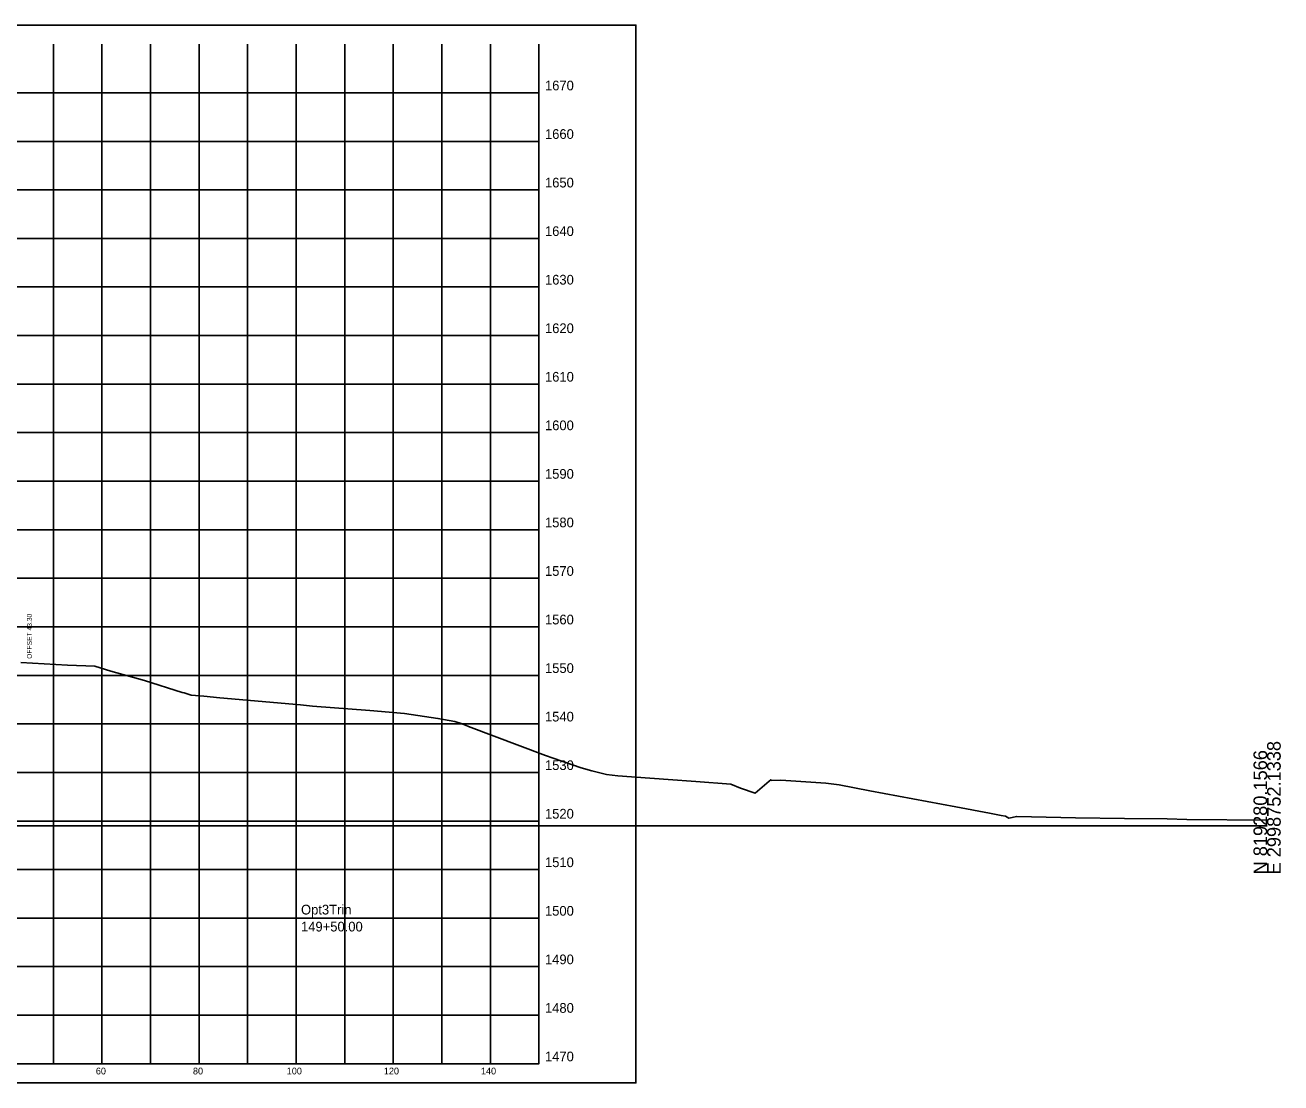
# Model space of a CAD drawing. Extents: x -26 to 603, y -10 to 4805.
# Drawn here: x 344.2 to 602.8, y 3947.1 to 4164.9 of the extents above; entities that cross this region are included whole.
import ezdxf

# ---------------------------------------------------------------- set-up
doc = ezdxf.new("R2010")
doc.units = 0
for name, color, linetype in [('DESIGN - SHEET - Corner Text', 7, 'Continuous'), ('DESIGN - SHEET - Light Grid', 7, 'Continuous'), ('DESIGN - SHEET - Linework', 7, 'Continuous'), ('DESIGN - SHEET - Plot Shape', 7, 'Continuous'), ('DESIGN - TYPICAL - Slope Tie Text', 7, 'Continuous'), ('DESIGN - TYPICAL - Warning Text', 7, 'Continuous'), ('SURVEY - GROUND - Top of Ground', 7, 'Continuous')]:
    doc.layers.add(name, color=color, linetype=linetype)

msp = doc.modelspace()

# ---------------------------------------------------------------- linework, layer by layer
at = {"layer": 'DESIGN - SHEET - Light Grid'}
msp.add_line((300, 4000), (600, 4000), dxfattribs=at)
at = {"layer": 'DESIGN - SHEET - Linework'}
for p, q in [((350, 3951), (350, 4161)), ((360, 3951), (360, 4161)), ((370, 3951), (370, 4161)), ((380, 3951), (380, 4161)), ((390, 3951), (390, 4161)), ((400, 3951), (400, 4161)), ((410, 3951), (410, 4161)), ((420, 3951), (420, 4161)), ((430, 3951), (430, 4161)), ((440, 3951), (440, 4161)), ((150, 4151), (450, 4151)), ((150, 4141), (450, 4141)), ((150, 4131), (450, 4131)), ((150, 4121), (450, 4121)), ((150, 4111), (450, 4111)), ((150, 4101), (450, 4101)), ((150, 4091), (450, 4091)), ((150, 4081), (450, 4081)), ((150, 4071), (450, 4071)), ((150, 4061), (450, 4061)), ((150, 4051), (450, 4051)), ((150, 4041), (450, 4041)), ((150, 4031), (450, 4031)), ((150, 4021), (450, 4021)), ((150, 4011), (450, 4011)), ((150, 4001), (450, 4001)), ((150, 3991), (450, 3991)), ((150, 3981), (450, 3981)), ((150, 3971), (450, 3971)), ((150, 3961), (450, 3961))]:
    msp.add_line(p, q, dxfattribs=at)
msp.add_lwpolyline([(150, 4161), (150, 3951), (450, 3951), (450, 4161)], dxfattribs=at)
at = {"layer": 'DESIGN - SHEET - Plot Shape'}
msp.add_lwpolyline([(130, 4164.94), (470, 4164.94), (470, 3947.06), (130, 3947.06)], close=True, dxfattribs=at)
at = {"layer": 'SURVEY - GROUND - Top of Ground'}
msp.add_lwpolyline([(343.3, 4033.66), (352.9, 4033.12), (358.55, 4032.89), (361.83, 4031.89), (368.79, 4029.96), (376.55, 4027.47), (376.92, 4027.41), (378.36, 4026.94), (380.96, 4026.74), (384.3, 4026.39), (400.87, 4024.9), (403.34, 4024.69), (415.15, 4023.77), (422.35, 4023.17), (429.21, 4022.15), (432.7, 4021.53), (434.02, 4021.09), (434.87, 4020.77), (435.53, 4020.5), (451.35, 4014.5), (452.97, 4013.93), (458.7, 4011.98), (460.93, 4011.37), (463.91, 4010.59), (466.28, 4010.34), (476.66, 4009.54), (482.3, 4009.17), (489.57, 4008.58), (491.53, 4007.77), (494.52, 4006.74), (497.4, 4009.23), (497.8, 4009.49), (497.91, 4009.37), (499.85, 4009.38), (502.92, 4009.23), (509.12, 4008.83), (511.86, 4008.42), (518.18, 4007.22), (535.88, 4003.94), (542.8, 4002.65), (545.19, 4002.17), (546.11, 4002.01), (546.83, 4001.59), (548.43, 4001.94), (560.56, 4001.67), (570.66, 4001.53), (579.4, 4001.43), (583.49, 4001.32), (600, 4001.17)], dxfattribs=at)

# ---------------------------------------------------------------- texts
at = {"layer": 'DESIGN - SHEET - Corner Text'}
for s, height, p in [('1670', 2, (451.25, 4151.5)), ('1660', 2, (451.25, 4141.5)), ('1650', 2, (451.25, 4131.5)), ('1640', 2, (451.25, 4121.5)), ('1630', 2, (451.25, 4111.5)), ('1620', 2, (451.25, 4101.5)), ('1610', 2, (451.25, 4091.5)), ('1600', 2, (451.25, 4081.5)), ('1590', 2, (451.25, 4071.5)), ('1580', 2, (451.25, 4061.5)), ('1570', 2, (451.25, 4051.5)), ('1560', 2, (451.25, 4041.5)), ('1550', 2, (451.25, 4031.5)), ('1540', 2, (451.25, 4021.5)), ('1530', 2, (451.25, 4011.5)), ('1520', 2, (451.25, 4001.5)), ('1510', 2, (451.25, 3991.5)), ('1500', 2, (451.25, 3981.5)), ('1490', 2, (451.25, 3971.5)), ('1480', 2, (451.25, 3961.5)), ('1470', 2, (451.25, 3951.5)), ('60', 1.4, (358.74, 3948.8)), ('80', 1.4, (378.74, 3948.8)), ('100', 1.4, (398.06, 3948.8)), ('120', 1.4, (418.06, 3948.8)), ('140', 1.4, (438.06, 3948.8))]:
    msp.add_text(s, height=height, dxfattribs=at).set_placement(p)
at = {"layer": 'DESIGN - SHEET - Light Grid'}
for s, p in [('E 2998752.1338', (602.8, 3990)), ('N 819280.1566', (600, 3990))]:
    msp.add_text(s, height=2.8, rotation=90, dxfattribs=at).set_placement(p)
at = {"layer": 'DESIGN - TYPICAL - Slope Tie Text'}
msp.add_text('OFFSET 43.30', height=1, rotation=90, dxfattribs=at).set_placement((345.55, 4034.41))
at = {"layer": 'DESIGN - TYPICAL - Warning Text'}
for s, p in [('Opt3Trin', (401, 3981.75)), ('149+50.00', (401, 3978.25))]:
    msp.add_text(s, height=2, dxfattribs=at).set_placement(p)

doc.saveas('drawing.dxf')
